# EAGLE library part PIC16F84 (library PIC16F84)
Microcontroller 8-bit, Flash/EEPROM
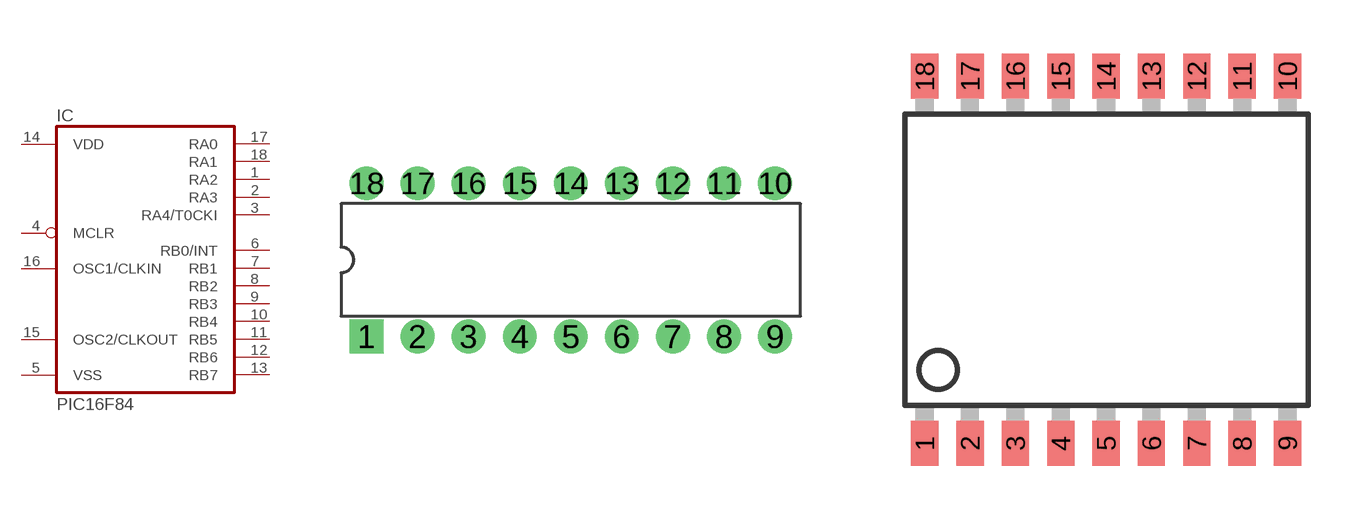
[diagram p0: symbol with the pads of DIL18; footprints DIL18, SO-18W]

Designator prefix IC

## PIC16F84P  [DIL18]
1  RA2
2  RA3
3  RA4/T0CKI  in
4  MCLR  in
5  VSS  pwr
6  RB0/INT
7  RB1
8  RB2
9  RB3
10  RB4
11  RB5
12  RB6
13  RB7
14  VDD  pwr
15  OSC2/CLKOUT  out
16  OSC1/CLKIN  in
17  RA0
18  RA1

## PIC16F84SO  [SO-18W]
Pads as for DIL18

## Footprint DIL18 (pad centres in mm)
Dual In Line Package
drill 0.813 pad 1.676 square: 1 -10.16,-3.81
drill 0.813 pad 1.676 round: 2 -7.62,-3.81; 3 -5.08,-3.81; 4 -2.54,-3.81; 5 0,-3.81; 6 2.54,-3.81; 7 5.08,-3.81; 8 7.62,-3.81; 9 10.16,-3.81; 10 10.16,3.81; 11 7.62,3.81; 12 5.08,3.81; 13 2.54,3.81; 14 0,3.81; 15 -2.54,3.81; 16 -5.08,3.81; 17 -7.62,3.81; 18 -10.16,3.81

## Footprint SO-18W (pad centres in mm)
Small Outline Package 300-mil body, package type SO
smd 0.762 x 1.27: 1 -5.08,-5.207; 2 -3.81,-5.207; 3 -2.54,-5.207; 4 -1.27,-5.207; 5 0,-5.207; 6 1.27,-5.207; 7 2.54,-5.207; 8 3.81,-5.207; 9 5.08,-5.207; 10 5.08,5.08; 11 3.81,5.08; 12 2.54,5.08; 13 1.27,5.08; 14 0,5.08; 15 -1.27,5.08; 16 -2.54,5.08; 17 -3.81,5.08; 18 -5.08,5.08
